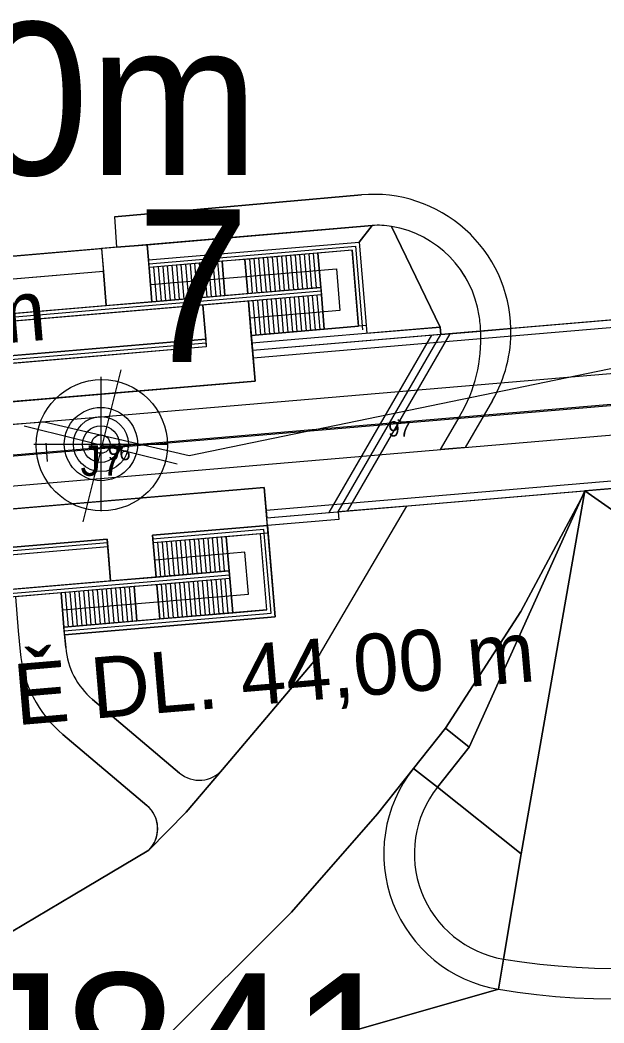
# Model space of a CAD drawing. Extents: x -606444 to -604546, y -1158114 to -1156869.
# Drawn here: x -605493.1 to -605454.9, y -1157172.8 to -1157107.1 of the extents above; entities that cross this region are included whole.
import ezdxf

# ---------------------------------------------------------------- set-up
doc = ezdxf.new("R2010")
doc.units = 0
for name, color, linetype in [('0_sondy', 7, 'Continuous'), ('ARCHIVNÍ SONDY', 7, 'Continuous'), ('B_CHOD', 7, 'Continuous'), ('B_TRAM', 7, 'Continuous'), ('B_VOZ', 7, 'Continuous'), ('B_ZELEN', 7, 'Continuous'), ('geofyzikální profily_předběžný GTP', 7, 'Continuous'), ('jádrové vrty_předběžný GTP', 7, 'Continuous'), ('netisk2', 7, 'Continuous'), ('NS_VB', 7, 'Continuous'), ('NS_VB_OBJ', 7, 'Continuous'), ('NS_VB_POP', 7, 'Continuous'), ('NS_VB_SVAHY', 7, 'Continuous'), ('OSA', 7, 'Continuous'), ('OSAPOP', 7, 'Continuous'), ('podélný profil trasou tramvaje', 7, 'Continuous'), ('sondy současného průzkumu', 7, 'Continuous')]:
    doc.layers.add(name, color=color, linetype=linetype)

# ---------------------------------------------------------------- blocks, each defined once
blk = doc.blocks.new('709')
for p, q in [((0, 2.2), (0, -2.2)), ((-2.2, 0), (2.2, 0))]:
    blk.add_line(p, q)
for radius in [1.2, 0.9, 0.6, 0.3]:
    blk.add_circle((0, 0), radius)
blk = doc.blocks.new('IG vrt podr')
at = {"layer": 'sondy současného průzkumu'}
for p, q in [((0.412, 1.649), (-0.418, -1.672)), ((-1.698, 0.422), (1.644, -0.408))]:
    blk.add_line(p, q, dxfattribs=at)
blk.add_circle((-0.002, 0.001), 1.434, dxfattribs=at)

msp = doc.modelspace()

# ---------------------------------------------------------------- linework, layer by layer
for p, q in [((-605468.29, -1157133.36), (-605468.39, -1157133.26)), ((-605468.29, -1157133.36), (-605468.39, -1157133.46)), ((-605468.29, -1157133.36), (-605468.19, -1157133.26)), ((-605468.29, -1157133.36), (-605468.19, -1157133.46)), ((-605487.787, -1157134.934), (-605487.887, -1157134.834)), ((-605487.787, -1157134.934), (-605487.687, -1157134.834)), ((-605486.62, -1157134.91), (-605486.72, -1157134.81)), ((-605486.62, -1157134.91), (-605486.52, -1157134.81)), ((-605487.787, -1157134.934), (-605487.887, -1157135.034)), ((-605487.787, -1157134.934), (-605487.687, -1157135.034)), ((-605486.62, -1157134.91), (-605486.72, -1157135.01)), ((-605486.62, -1157134.91), (-605486.52, -1157135.01))]:
    msp.add_line(p, q)
at = {"layer": 'B_CHOD'}
for points in [[(-605470.779, -1157118.526), (-605486.95, -1157119.96)], [(-605486.95, -1157119.96), (-605486.82, -1157121.962), (-605484.821, -1157121.792), (-605470.073, -1157120.538)], [(-605487.81, -1157122.046), (-605487.683, -1157123.541), (-605487.492, -1157125.783), (-605484.503, -1157125.528), (-605484.694, -1157123.286), (-605484.821, -1157121.792), (-605486.82, -1157121.962), (-605487.81, -1157122.046)], [(-605473.634, -1157122.346), (-605478.417, -1157122.753), (-605478.226, -1157124.994), (-605473.443, -1157124.588), (-605473.634, -1157122.346)], [(-605471.392, -1157122.155), (-605473.634, -1157122.346), (-605473.443, -1157124.588), (-605473.401, -1157125.086), (-605473.21, -1157127.328), (-605470.968, -1157127.137), (-605471.392, -1157122.155)], [(-605479.911, -1157122.88), (-605484.694, -1157123.286), (-605484.503, -1157125.528), (-605479.721, -1157125.122), (-605479.911, -1157122.88)], [(-605478.417, -1157122.753), (-605479.911, -1157122.88), (-605479.721, -1157125.122), (-605478.226, -1157124.994), (-605478.417, -1157122.753)], [(-605487.683, -1157123.541), (-605522.258, -1157126.481), (-605522.068, -1157128.723), (-605487.492, -1157125.783), (-605487.683, -1157123.541)], [(-605477.908, -1157128.731), (-605477.993, -1157127.735), (-605478.184, -1157125.493), (-605481.173, -1157125.747), (-605480.982, -1157127.989), (-605480.94, -1157128.487), (-605521.792, -1157131.962), (-605521.58, -1157134.453), (-605477.739, -1157130.724), (-605477.908, -1157128.731)], [(-605477.993, -1157127.735), (-605473.21, -1157127.328), (-605473.401, -1157125.086), (-605478.184, -1157125.493), (-605477.993, -1157127.735)], [(-605521.835, -1157131.463), (-605480.982, -1157127.989), (-605481.173, -1157125.747), (-605522.025, -1157129.221), (-605521.835, -1157131.463)], [(-605462.962, -1157127.46), (-605460.987, -1157127.292)], [(-605487.446, -1157141.084), (-605487.403, -1157141.582), (-605487.213, -1157143.824), (-605484.223, -1157143.57), (-605484.414, -1157141.328), (-605484.456, -1157140.829), (-605476.934, -1157140.19), (-605477.145, -1157137.699), (-605520.987, -1157141.427), (-605520.818, -1157143.42), (-605520.775, -1157143.918), (-605487.446, -1157141.084)], [(-605477.389, -1157140.73), (-605479.631, -1157140.921), (-605479.441, -1157143.163), (-605479.398, -1157143.661), (-605479.208, -1157145.903), (-605476.966, -1157145.712), (-605477.389, -1157140.73)], [(-605479.631, -1157140.921), (-605484.414, -1157141.328), (-605484.223, -1157143.57), (-605479.441, -1157143.163), (-605479.631, -1157140.921)], [(-605487.403, -1157141.582), (-605528.256, -1157145.056), (-605528.065, -1157147.298), (-605487.213, -1157143.824), (-605487.403, -1157141.582)], [(-605483.99, -1157146.31), (-605479.208, -1157145.903), (-605479.398, -1157143.661), (-605484.181, -1157144.068), (-605483.99, -1157146.31)], [(-605490.153, -1157148.189), (-605490.268, -1157146.844), (-605490.458, -1157144.602), (-605493.448, -1157144.856), (-605493.257, -1157147.098), (-605493.142, -1157148.443)], [(-605490.268, -1157146.844), (-605485.485, -1157146.437), (-605485.676, -1157144.195), (-605490.458, -1157144.602), (-605490.268, -1157146.844)], [(-605485.485, -1157146.437), (-605483.99, -1157146.31), (-605484.181, -1157144.068), (-605485.676, -1157144.195), (-605485.485, -1157146.437)], [(-605482.694, -1157156.408), (-605488.4, -1157151.583)], [(-605490.337, -1157153.873), (-605484.836, -1157158.526)], [(-605465.28, -1157153.47), (-605467.365, -1157156.1), (-605465.798, -1157157.342), (-605463.713, -1157154.713), (-605465.28, -1157153.47)], [(-605484.706, -1157161.461), (-605482.25, -1157158.98), (-605479.876, -1157156.173)], [(-605465.798, -1157157.342), (-605467.365, -1157156.1)], [(-605461.469, -1157168.595), (-605461.799, -1157170.567)], [(-605461.799, -1157170.567), (-605461.469, -1157168.595)]]:
    msp.add_lwpolyline(points, dxfattribs=at)
for centre, radius, start, end in [((-605469.985, -1157127.491), 9, 1.26936, 95.06647), ((-605469.649, -1157125.52), 5, 80.34441, 94.8613), ((-605469.985, -1157127.491), 7, 8.62008, 80.34447), ((-605472.951, -1157127.941), 10, 2.75719, 8.62025), ((-605485.171, -1157147.765), 8, 184.8613, 229.7761), ((-605485.171, -1157147.765), 5, 184.8613, 229.7761), ((-605481.403, -1157154.881), 2, 229.7761, 319.7761), ((-605460.313, -1157161.691), 9, 141.59061, 260.49211), ((-605460.313, -1157161.691), 7, 141.59061, 260.49211), ((-605486.127, -1157160.053), 2, 315.28224, 49.7761), ((-605454.118, -1157124.706), 44.5, 260.49211, 309.36649), ((-605454.118, -1157124.706), 46.5, 260.49211, 309.36649), ((-605454.118, -1157124.706), 53.5, 247.64912, 309.36649)]:
    msp.add_arc(centre, radius, start, end, dxfattribs=at)
at = {"layer": 'B_TRAM'}
for p, q in [((-605374.614, -1157119.946), (-605477.908, -1157128.731)), ((-605477.908, -1157128.731), (-605477.739, -1157130.724)), ((-605477.739, -1157130.724), (-605521.58, -1157134.453)), ((-605476.976, -1157139.691), (-605373.68, -1157130.906)), ((-605520.987, -1157141.427), (-605477.145, -1157137.699)), ((-605477.145, -1157137.699), (-605476.976, -1157139.691))]:
    msp.add_line(p, q, dxfattribs=at)
at = {"layer": 'B_VOZ'}
for points in [[(-605467.365, -1157156.1), (-605469.72, -1157159.07), (-605475.36, -1157165.52), (-605483.87, -1157174.01), (-605485.965, -1157175.495)], [(-605467.365, -1157156.1), (-605467.365, -1157156.1)], [(-605461.799, -1157170.567), (-605474.463, -1157174.187)], [(-605474.463, -1157174.187), (-605461.799, -1157170.567)]]:
    msp.add_lwpolyline(points, dxfattribs=at)
for centre, radius, start, end in [((-605460.313, -1157161.691), 9, 141.59102, 260.49211), ((-605460.313, -1157161.691), 9, 141.59061, 141.59102), ((-605454.118, -1157124.706), 46.5, 260.49211, 309.36649), ((-605454.118, -1157124.706), 53.5, 247.64912, 309.36649)]:
    msp.add_arc(centre, radius, start, end, dxfattribs=at)
at = {"layer": 'B_ZELEN'}
for p, q in [((-605502.45, -1157123.32), (-605487.81, -1157122.046)), ((-605487.81, -1157122.046), (-605487.683, -1157123.541)), ((-605487.683, -1157123.541), (-605496.651, -1157124.303))]:
    msp.add_line(p, q, dxfattribs=at)
for points in [[(-605484.736, -1157122.788), (-605470.936, -1157121.615), (-605470.073, -1157120.538), (-605484.821, -1157121.792), (-605484.736, -1157122.788)], [(-605470.073, -1157120.538), (-605470.936, -1157121.615), (-605470.428, -1157127.593)], [(-605470.428, -1157127.593), (-605465.621, -1157127.184), (-605468.811, -1157120.59)], [(-605468.811, -1157120.59), (-605465.621, -1157127.184), (-605465.578, -1157127.682), (-605462.962, -1157127.46)], [(-605373.68, -1157130.906), (-605456.139, -1157137.919), (-605425.893, -1157159.109)], [(-605463.713, -1157154.713), (-605465.798, -1157157.342), (-605460.313, -1157161.691), (-605456.139, -1157137.919), (-605463.713, -1157154.713)], [(-605465.28, -1157153.47), (-605463.713, -1157154.713), (-605456.139, -1157137.919), (-605456.39, -1157138.45), (-605460.33, -1157145.83), (-605465.28, -1157153.47)], [(-605425.893, -1157159.109), (-605456.139, -1157137.919), (-605460.313, -1157161.691), (-605461.469, -1157168.595)], [(-605479.876, -1157156.173), (-605473.53, -1157148.67), (-605467.797, -1157138.911), (-605472.296, -1157139.293), (-605472.253, -1157139.792), (-605476.934, -1157140.19), (-605476.425, -1157146.168), (-605490.225, -1157147.342), (-605490.153, -1157148.189)], [(-605488.4, -1157151.583), (-605482.694, -1157156.408)], [(-605484.836, -1157158.526), (-605490.337, -1157153.873)], [(-605461.469, -1157168.595), (-605460.313, -1157161.691), (-605465.798, -1157157.342)], [(-605595.569, -1157184.021), (-605592.294, -1157180.09), (-605579.33, -1157177.48), (-605552.67, -1157174.72), (-605533.88, -1157173.88), (-605512.92, -1157173.16), (-605498.57, -1157169.69), (-605484.706, -1157161.461)]]:
    msp.add_lwpolyline(points, dxfattribs=at)
for centre, radius, start, end in [((-605469.649, -1157125.52), 5, 80.34461, 94.8613), ((-605469.985, -1157127.491), 7, 8.62083, 80.34461), ((-605472.951, -1157127.941), 10, 2.75719, 8.62077), ((-605485.171, -1157147.765), 8, 184.8613, 229.7761), ((-605485.171, -1157147.765), 5, 184.8613, 229.7761), ((-605481.403, -1157154.881), 2, 229.7761, 319.7761), ((-605460.313, -1157161.691), 7, 141.59061, 260.49211), ((-605486.127, -1157160.053), 2, 359.99989, 49.7761), ((-605454.118, -1157124.706), 44.5, 260.49211, 309.36649), ((-605486.127, -1157160.053), 2, 315.28295, 359.99989)]:
    msp.add_arc(centre, radius, start, end, dxfattribs=at)
at = {"layer": 'geofyzikální profily_předběžný GTP'}
msp.add_lwpolyline([(-605670.777, -1157141.05), (-605656.017, -1157139.471), (-605613.877, -1157139.359), (-605584.802, -1157137.32), (-605531.406, -1157136.329), (-605491.561, -1157133.405), (-605482.073, -1157135.613), (-605438.781, -1157126.664), (-605383.232, -1157124.522), (-605352.341, -1157123.33), (-605321.946, -1157125.999), (-605284.139, -1157130.42), (-605243.303, -1157142.595), (-605207.83, -1157158.833), (-605179.979, -1157186.151), (-605165.292, -1157202.666), (-605149.231, -1157223.341), (-605135.067, -1157244.471), (-605115.915, -1157286.275), (-605103.218, -1157315.843), (-605095.331, -1157330.321), (-605036.966, -1157403.361), (-604999.079, -1157442.536), (-604970.798, -1157468.352)], dxfattribs=at)
at = {"layer": 'netisk2'}
msp.add_line((-605487.847, -1157134.855), (-605487.827, -1157135.095), dxfattribs=at)
at = {"layer": 'NS_VB'}
for p, q in [((-605486.95, -1157119.96), (-605470.779, -1157118.526)), ((-605486.95, -1157119.96), (-605486.82, -1157121.962)), ((-605470.073, -1157120.538), (-605499.97, -1157123.08)), ((-605484.736, -1157122.788), (-605470.936, -1157121.615)), ((-605470.936, -1157121.615), (-605470.428, -1157127.593)), ((-605487.81, -1157122.046), (-605487.492, -1157125.783)), ((-605484.821, -1157121.792), (-605484.503, -1157125.528)), ((-605471.392, -1157122.155), (-605484.694, -1157123.286)), ((-605473.634, -1157122.346), (-605473.21, -1157127.328)), ((-605471.392, -1157122.155), (-605470.968, -1157127.137)), ((-605479.911, -1157122.88), (-605479.721, -1157125.122)), ((-605478.417, -1157122.753), (-605478.226, -1157124.994)), ((-605487.683, -1157123.541), (-605524.5, -1157126.672)), ((-605478.184, -1157125.493), (-605477.739, -1157130.724)), ((-605481.173, -1157125.747), (-605480.94, -1157128.487)), ((-605465.578, -1157127.682), (-605465.621, -1157127.184)), ((-605472.903, -1157139.345), (-605466.176, -1157127.717)), ((-605480.94, -1157128.487), (-605524.532, -1157132.195)), ((-605462.194, -1157131.998), (-605463.973, -1157135.073)), ((-605464.328, -1157133.006), (-605465.625, -1157135.213)), ((-605463.973, -1157135.073), (-605465.625, -1157135.213)), ((-605476.425, -1157146.168), (-605477.145, -1157137.699)), ((-605456.39, -1157138.45), (-605456.139, -1157137.919)), ((-605460.33, -1157145.83), (-605456.39, -1157138.45)), ((-605473.53, -1157148.67), (-605467.797, -1157138.911)), ((-605472.296, -1157139.293), (-605472.253, -1157139.792)), ((-605472.253, -1157139.792), (-605484.456, -1157140.829)), ((-605476.966, -1157145.712), (-605477.389, -1157140.73)), ((-605487.446, -1157141.084), (-605530.54, -1157144.749)), ((-605487.213, -1157143.824), (-605487.446, -1157141.084)), ((-605484.456, -1157140.829), (-605484.223, -1157143.57)), ((-605479.208, -1157145.903), (-605479.631, -1157140.921)), ((-605490.153, -1157148.189), (-605490.458, -1157144.602)), ((-605485.485, -1157146.437), (-605485.676, -1157144.195)), ((-605483.99, -1157146.31), (-605484.181, -1157144.068)), ((-605476.966, -1157145.712), (-605490.268, -1157146.844)), ((-605465.28, -1157153.47), (-605460.33, -1157145.83)), ((-605490.225, -1157147.342), (-605476.425, -1157146.168)), ((-605473.53, -1157148.67), (-605479.876, -1157156.173)), ((-605482.694, -1157156.408), (-605488.4, -1157151.583)), ((-605484.836, -1157158.526), (-605490.337, -1157153.873)), ((-605467.365, -1157156.1), (-605465.28, -1157153.47)), ((-605465.28, -1157153.47), (-605463.713, -1157154.713)), ((-605465.798, -1157157.342), (-605463.713, -1157154.713)), ((-605479.876, -1157156.173), (-605482.25, -1157158.98)), ((-605469.72, -1157159.07), (-605467.365, -1157156.1)), ((-605482.25, -1157158.98), (-605484.706, -1157161.461)), ((-605475.36, -1157165.52), (-605469.72, -1157159.07)), ((-605484.706, -1157161.461), (-605498.57, -1157169.69)), ((-605483.87, -1157174.01), (-605475.36, -1157165.52))]:
    msp.add_line(p, q, dxfattribs=at)
for points in [[(-605374.614, -1157119.946), (-605477.908, -1157128.731)], [(-605473.443, -1157124.588), (-605522.068, -1157128.723)], [(-605473.401, -1157125.086), (-605522.025, -1157129.221)], [(-605470.47, -1157127.095), (-605477.993, -1157127.735)], [(-605465.621, -1157127.184), (-605477.951, -1157128.233)], [(-605480.982, -1157127.989), (-605524.077, -1157131.654)], [(-605471.688, -1157139.242), (-605464.971, -1157127.631)], [(-605477.739, -1157130.724), (-605521.58, -1157134.453)], [(-605476.976, -1157139.691), (-605373.68, -1157130.906)], [(-605477.145, -1157137.699), (-605520.987, -1157141.427)], [(-605476.891, -1157140.688), (-605484.414, -1157141.328)], [(-605487.403, -1157141.582), (-605530.498, -1157145.247)], [(-605479.441, -1157143.163), (-605528.065, -1157147.298)], [(-605479.398, -1157143.661), (-605528.023, -1157147.796)]]:
    msp.add_lwpolyline(points, dxfattribs=at)
for centre, radius, start, end in [((-605469.985, -1157127.491), 9, 1.26936, 95.06647), ((-605469.649, -1157125.52), 5, 80.34461, 94.8613), ((-605469.985, -1157127.491), 7, 8.62063, 80.34461), ((-605472.951, -1157127.941), 10, 2.75719, 8.62063), ((-605472.951, -1157127.941), 10, 329.56842, 2.75719), ((-605469.985, -1157127.491), 9, 329.95009, 1.26936), ((-605485.171, -1157147.765), 8, 184.8613, 229.7761), ((-605485.171, -1157147.765), 5, 184.8613, 229.7761), ((-605481.403, -1157154.881), 2, 229.7761, 319.7761), ((-605460.313, -1157161.691), 9, 141.59061, 260.49211), ((-605460.313, -1157161.691), 7, 141.59061, 260.49211), ((-605486.127, -1157160.053), 2, 315.28224, 49.7761), ((-605454.118, -1157124.706), 44.5, 260.49211, 309.36649), ((-605454.118, -1157124.706), 46.5, 260.49211, 309.36649), ((-605454.118, -1157124.706), 53.5, 247.64912, 309.36649)]:
    msp.add_arc(centre, radius, start, end, dxfattribs=at)
at = {"layer": 'NS_VB_OBJ'}
for points in [[(-605374.572, -1157120.444), (-605477.866, -1157129.229)], [(-605484.715, -1157123.037), (-605471.164, -1157121.885), (-605470.698, -1157127.365)], [(-605480.961, -1157128.238), (-605524.304, -1157131.924), (-605524.771, -1157126.444), (-605496.672, -1157124.054)], [(-605473.422, -1157124.837), (-605522.046, -1157128.972)], [(-605465.621, -1157127.184), (-605477.951, -1157128.233)], [(-605472.296, -1157139.293), (-605465.578, -1157127.682)], [(-605477.018, -1157139.193), (-605373.722, -1157130.408)], [(-605472.253, -1157139.792), (-605476.934, -1157140.19)], [(-605490.246, -1157147.093), (-605476.695, -1157145.94), (-605477.162, -1157140.46), (-605484.435, -1157141.079)], [(-605487.424, -1157141.333), (-605530.519, -1157144.998)], [(-605528.044, -1157147.547), (-605479.419, -1157143.412)]]:
    msp.add_lwpolyline(points, dxfattribs=at)
at = {"layer": 'NS_VB_SVAHY'}
for p, q in [((-605481.406, -1157123.007), (-605481.215, -1157125.249)), ((-605481.107, -1157122.981), (-605480.916, -1157125.223)), ((-605480.808, -1157122.956), (-605480.617, -1157125.198)), ((-605480.509, -1157122.931), (-605480.318, -1157125.172)), ((-605480.21, -1157122.905), (-605480.019, -1157125.147)), ((-605478.118, -1157122.727), (-605477.927, -1157124.969)), ((-605477.819, -1157122.702), (-605477.628, -1157124.944)), ((-605477.52, -1157122.676), (-605477.329, -1157124.918)), ((-605477.221, -1157122.651), (-605477.03, -1157124.893)), ((-605476.922, -1157122.625), (-605476.731, -1157124.867)), ((-605476.623, -1157122.6), (-605476.432, -1157124.842)), ((-605476.324, -1157122.575), (-605476.133, -1157124.816)), ((-605476.025, -1157122.549), (-605475.835, -1157124.791)), ((-605475.726, -1157122.524), (-605475.536, -1157124.766)), ((-605475.427, -1157122.498), (-605475.237, -1157124.74)), ((-605475.128, -1157122.473), (-605474.938, -1157124.715)), ((-605474.83, -1157122.447), (-605474.639, -1157124.689)), ((-605474.531, -1157122.422), (-605474.34, -1157124.664)), ((-605474.232, -1157122.397), (-605474.041, -1157124.639)), ((-605473.933, -1157122.371), (-605473.742, -1157124.613)), ((-605484.395, -1157123.261), (-605484.204, -1157125.503)), ((-605484.096, -1157123.236), (-605483.905, -1157125.478)), ((-605483.797, -1157123.21), (-605483.607, -1157125.452)), ((-605483.498, -1157123.185), (-605483.308, -1157125.427)), ((-605483.199, -1157123.159), (-605483.009, -1157125.401)), ((-605482.9, -1157123.134), (-605482.71, -1157125.376)), ((-605482.602, -1157123.108), (-605482.411, -1157125.35)), ((-605482.303, -1157123.083), (-605482.112, -1157125.325)), ((-605482.004, -1157123.058), (-605481.813, -1157125.3)), ((-605481.705, -1157123.032), (-605481.514, -1157125.274)), ((-605477.885, -1157125.467), (-605477.694, -1157127.709)), ((-605477.586, -1157125.442), (-605477.395, -1157127.684)), ((-605477.287, -1157125.416), (-605477.096, -1157127.658)), ((-605476.988, -1157125.391), (-605476.797, -1157127.633)), ((-605476.689, -1157125.366), (-605476.498, -1157127.607)), ((-605476.39, -1157125.34), (-605476.199, -1157127.582)), ((-605476.091, -1157125.315), (-605475.9, -1157127.557)), ((-605475.792, -1157125.289), (-605475.602, -1157127.531)), ((-605475.493, -1157125.264), (-605475.303, -1157127.506)), ((-605475.194, -1157125.238), (-605475.004, -1157127.48)), ((-605474.895, -1157125.213), (-605474.705, -1157127.455)), ((-605474.597, -1157125.188), (-605474.406, -1157127.429)), ((-605474.298, -1157125.162), (-605474.107, -1157127.404)), ((-605473.999, -1157125.137), (-605473.808, -1157127.379)), ((-605473.7, -1157125.111), (-605473.509, -1157127.353)), ((-605483.924, -1157143.544), (-605484.115, -1157141.302)), ((-605483.626, -1157143.519), (-605483.816, -1157141.277)), ((-605483.327, -1157143.493), (-605483.517, -1157141.251)), ((-605483.028, -1157143.468), (-605483.218, -1157141.226)), ((-605482.729, -1157143.442), (-605482.919, -1157141.201)), ((-605482.43, -1157143.417), (-605482.621, -1157141.175)), ((-605482.131, -1157143.392), (-605482.322, -1157141.15)), ((-605481.832, -1157143.366), (-605482.023, -1157141.124)), ((-605481.533, -1157143.341), (-605481.724, -1157141.099)), ((-605481.234, -1157143.315), (-605481.425, -1157141.073)), ((-605480.935, -1157143.29), (-605481.126, -1157141.048)), ((-605480.636, -1157143.264), (-605480.827, -1157141.023)), ((-605480.337, -1157143.239), (-605480.528, -1157140.997)), ((-605480.038, -1157143.214), (-605480.229, -1157140.972)), ((-605479.74, -1157143.188), (-605479.93, -1157140.946)), ((-605483.691, -1157146.284), (-605483.882, -1157144.042)), ((-605483.393, -1157146.259), (-605483.583, -1157144.017)), ((-605483.094, -1157146.233), (-605483.284, -1157143.991)), ((-605482.795, -1157146.208), (-605482.985, -1157143.966)), ((-605482.496, -1157146.183), (-605482.686, -1157143.941)), ((-605482.197, -1157146.157), (-605482.387, -1157143.915)), ((-605481.898, -1157146.132), (-605482.089, -1157143.89)), ((-605481.599, -1157146.106), (-605481.79, -1157143.864)), ((-605481.3, -1157146.081), (-605481.491, -1157143.839)), ((-605481.001, -1157146.055), (-605481.192, -1157143.813)), ((-605480.702, -1157146.03), (-605480.893, -1157143.788)), ((-605480.403, -1157146.005), (-605480.594, -1157143.763)), ((-605480.104, -1157145.979), (-605480.295, -1157143.737)), ((-605479.805, -1157145.954), (-605479.996, -1157143.712)), ((-605479.507, -1157145.928), (-605479.697, -1157143.686)), ((-605489.969, -1157146.818), (-605490.159, -1157144.576)), ((-605489.67, -1157146.793), (-605489.861, -1157144.551)), ((-605489.371, -1157146.767), (-605489.562, -1157144.525)), ((-605489.072, -1157146.742), (-605489.263, -1157144.5)), ((-605488.773, -1157146.716), (-605488.964, -1157144.474)), ((-605488.474, -1157146.691), (-605488.665, -1157144.449)), ((-605488.175, -1157146.666), (-605488.366, -1157144.424)), ((-605487.876, -1157146.64), (-605488.067, -1157144.398)), ((-605487.577, -1157146.615), (-605487.768, -1157144.373)), ((-605487.278, -1157146.589), (-605487.469, -1157144.347)), ((-605486.98, -1157146.564), (-605487.17, -1157144.322)), ((-605486.681, -1157146.538), (-605486.871, -1157144.297)), ((-605486.382, -1157146.513), (-605486.572, -1157144.271)), ((-605486.083, -1157146.488), (-605486.273, -1157144.246)), ((-605485.784, -1157146.462), (-605485.975, -1157144.22))]:
    msp.add_line(p, q, dxfattribs=at)
for points in [[(-605484.599, -1157124.407), (-605472.418, -1157123.371), (-605472.185, -1157126.112), (-605478.088, -1157126.614)], [(-605490.363, -1157145.723), (-605478.182, -1157144.687), (-605478.415, -1157141.946), (-605484.319, -1157142.449)]]:
    msp.add_lwpolyline(points, dxfattribs=at)
at = {"layer": 'OSA'}
msp.add_line((-605374.147, -1157125.426), (-605584.296, -1157143.299), dxfattribs=at)
for points in [[(-605374.317, -1157123.433), (-605584.465, -1157141.306)], [(-605584.127, -1157145.292), (-605373.977, -1157127.419)]]:
    msp.add_lwpolyline(points, dxfattribs=at)
at = {"layer": 'OSAPOP'}
msp.add_line((-605491.341, -1157135.996), (-605491.443, -1157134.8), dxfattribs=at)
at = {"layer": 'podélný profil trasou tramvaje'}
msp.add_lwpolyline([(-605358.234, -1157124.224), (-605590.305, -1157143.817), (-605624.537, -1157148.594), (-605648.212, -1157155.583), (-605668.251, -1157164.472)], dxfattribs=at)

# ---------------------------------------------------------------- block references
at = {"layer": '0_sondy', "xscale": 2, "yscale": 2}
msp.add_blockref('709', (-605487.847, -1157134.855), dxfattribs=at)
at = {"layer": 'jádrové vrty_předběžný GTP', "xscale": 3, "yscale": 3}
msp.add_blockref('IG vrt podr', (-605487.782, -1157134.934), dxfattribs=at)

# ---------------------------------------------------------------- texts
for s, height, p in [('97', 1, (-605469.026, -1157134.36)), ('J7', 2, (-605489.181, -1157136.934)), ('96', 1, (-605487.384, -1157135.91))]:
    msp.add_text(s, height=height).set_placement(p)
at = {"layer": '0_sondy'}
msp.add_text('7', height=10, dxfattribs=at).set_placement((-605485.531, -1157129.467))
at = {"layer": 'ARCHIVNÍ SONDY'}
msp.add_text('J841', height=10, dxfattribs=at).set_placement((-605497.004, -1157179.524))
at = {"layer": 'jádrové vrty_předběžný GTP'}
msp.add_text('J7, 10m', height=10, dxfattribs=at).set_placement((-605525.056, -1157117.222))
at = {"layer": 'NS_VB_POP'}
for p in [(-605555.286, -1157133.455), (-605523.276, -1157155.823)]:
    msp.add_text('NÁSTUPIŠTĚ DL. 44,00 m', height=4, rotation=4.8613, dxfattribs=at).set_placement(p)

doc.saveas('drawing.dxf')
